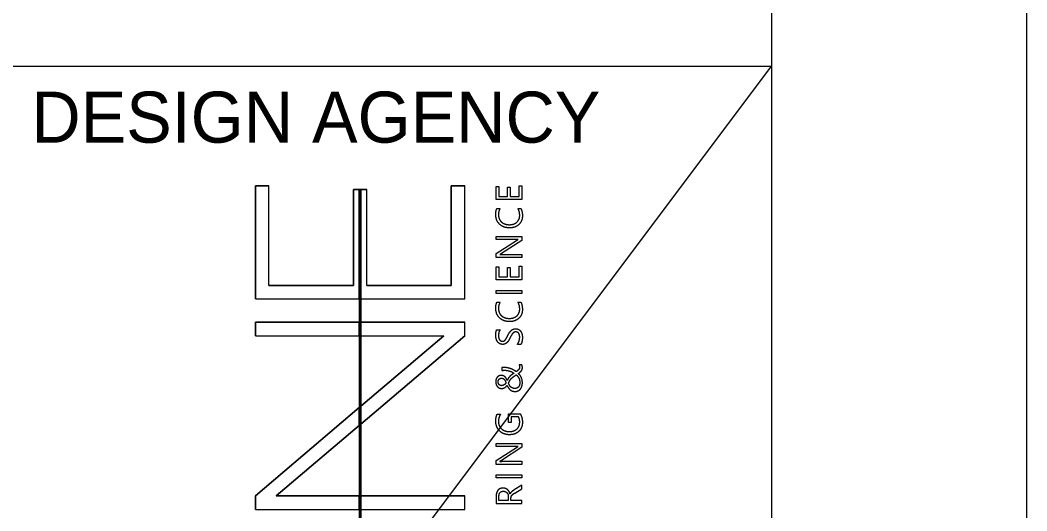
# Model space of a CAD drawing. Extents: x 0 to 34, y 0 to 30.9.
# Drawn here: x 32.028 to 34, y 4.129 to 5.09 of the extents above; entities that cross this region are included whole.
import ezdxf

# ---------------------------------------------------------------- set-up
doc = ezdxf.new("R2010")
doc.units = 0
for name, color, linetype in [('SC_Scratch1', 7, 'Continuous'), ('SH_Border', 7, 'Continuous'), ('SH_Cut_Line', 7, 'Continuous'), ('SH_Data', 7, 'Continuous')]:
    doc.layers.add(name, color=color, linetype=linetype)

msp = doc.modelspace()

# ---------------------------------------------------------------- linework, layer by layer
at = {"layer": 'SC_Scratch1'}
msp.add_line((32, 3), (33.5, 5), dxfattribs=at)
at = {"layer": 'SH_Border'}
msp.add_line((32, 5), (33.5, 5), dxfattribs=at)
msp.add_lwpolyline([(1.5, 21.5), (33.5, 21.5), (33.5, 0.5), (1.5, 0.5)], close=True, dxfattribs=at)
at = {"layer": 'SH_Cut_Line'}
msp.add_lwpolyline([(0, 0), (34, 0), (34, 22), (0, 22)], close=True, dxfattribs=at)
at = {"layer": 'SH_Data'}
for p, q in [((32.489, 4.7652), (32.5153, 4.7652)), ((32.489, 4.5439), (32.489, 4.7652)), ((32.5153, 4.5702), (32.5153, 4.7652)), ((32.6807, 4.5702), (32.6807, 4.7581)), ((32.6807, 4.7581), (32.6923, 4.7581)), ((32.6923, 4.7581), (32.6923, 3.9731)), ((32.6923, 4.7581), (32.6923, 4.5439)), ((32.6923, 4.7581), (32.6954, 4.7581)), ((32.6954, 4.7581), (32.6954, 3.9731)), ((32.6954, 4.7581), (32.6954, 4.5439)), ((32.6954, 4.7581), (32.707, 4.7581)), ((32.707, 4.5702), (32.707, 4.7581)), ((32.8724, 4.7652), (32.8988, 4.7652)), ((32.8724, 4.5702), (32.8724, 4.7652)), ((32.8988, 4.5439), (32.8988, 4.7652)), ((32.9617, 4.7208), (32.968, 4.7208)), ((33.0032, 4.7208), (33.0089, 4.7208)), ((33.0035, 4.6602), (33.0035, 4.6603)), ((32.9676, 4.631), (32.9676, 4.6308)), ((32.5153, 4.5702), (32.6807, 4.5702)), ((32.707, 4.5702), (32.8724, 4.5702)), ((32.489, 4.5439), (32.6923, 4.5439)), ((32.6954, 4.5439), (32.8988, 4.5439)), ((32.9617, 4.5373), (32.968, 4.5373)), ((33.0032, 4.5373), (33.0089, 4.5373)), ((32.489, 4.4717), (32.489, 4.4981)), ((32.489, 4.4981), (32.6923, 4.4981)), ((32.6923, 4.4981), (32.6923, 4.4717)), ((32.6954, 4.4981), (32.6954, 4.4717)), ((32.6954, 4.4981), (32.8988, 4.4981)), ((32.8988, 4.4717), (32.8988, 4.4981)), ((32.9615, 4.4834), (32.9681, 4.4834)), ((32.489, 4.4717), (32.6923, 4.4717)), ((32.6954, 4.3337), (32.8577, 4.4717)), ((32.8988, 4.4717), (32.6954, 4.2989)), ((32.6954, 4.4717), (32.8577, 4.4717)), ((33.009, 4.4549), (33.002, 4.4549)), ((32.9715, 4.4092), (32.9715, 4.4036)), ((33.0109, 4.4148), (33.0055, 4.4148)), ((33.0118, 4.4094), (33.0118, 4.4094)), ((32.9709, 4.3886), (32.9709, 4.3886)), ((33.0068, 4.3798), (33.0068, 4.3798)), ((32.489, 4.158), (32.6923, 4.331)), ((32.6923, 4.331), (32.6923, 4.2962)), ((32.6954, 4.3337), (32.6954, 4.2989)), ((32.9623, 4.318), (32.9689, 4.318)), ((32.6923, 4.2962), (32.5296, 4.158)), ((33.0035, 4.255), (33.0035, 4.2551)), ((32.9676, 4.2258), (32.9676, 4.2256)), ((32.9877, 4.1622), (32.9876, 4.1622)), ((32.489, 4.1316), (32.489, 4.158)), ((32.5296, 4.158), (32.6923, 4.158)), ((32.6923, 4.158), (32.6923, 4.1316)), ((32.6954, 4.158), (32.6954, 4.1316)), ((32.6954, 4.158), (32.8988, 4.158)), ((32.8988, 4.1316), (32.8988, 4.158)), ((32.489, 4.1316), (32.6923, 4.1316)), ((32.6954, 4.1316), (32.8988, 4.1316))]:
    msp.add_line(p, q, dxfattribs=at)
for points in [[(32.489, 4.7652), (32.489, 4.5439), (32.6923, 4.5439), (32.6923, 4.7581), (32.6807, 4.7581), (32.6807, 4.5702), (32.5153, 4.5702), (32.5153, 4.7652)], [(32.707, 4.5702), (32.707, 4.7581), (32.6954, 4.7581), (32.6954, 4.5439), (32.8988, 4.5439), (32.8988, 4.7652), (32.8724, 4.7652), (32.8724, 4.5702)], [(33.011, 4.7652), (33.011, 4.7384), (32.9605, 4.7384), (32.9605, 4.7641), (32.9659, 4.7641), (32.9659, 4.7443), (32.9827, 4.7443), (32.9827, 4.7626), (32.988, 4.7626), (32.988, 4.7443), (33.0057, 4.7443), (33.0057, 4.7652)], [(33.011, 4.6081), (33.011, 4.5813), (32.9605, 4.5813), (32.9605, 4.607), (32.9659, 4.607), (32.9659, 4.5873), (32.9827, 4.5873), (32.9827, 4.6055), (32.988, 4.6055), (32.988, 4.5873), (33.0057, 4.5873), (33.0057, 4.6081)], [(33.011, 4.5607), (33.011, 4.5548), (32.9605, 4.5548), (32.9605, 4.5607)], [(32.489, 4.4981), (32.489, 4.4717), (32.6923, 4.4717), (32.6923, 4.4981)], [(32.6954, 4.4981), (32.6954, 4.4717), (32.8577, 4.4717), (32.6954, 4.3337), (32.6954, 4.2989), (32.8988, 4.4717), (32.8988, 4.4981)], [(32.489, 4.158), (32.489, 4.1316), (32.6923, 4.1316), (32.6923, 4.158), (32.5296, 4.158), (32.6923, 4.2962), (32.6923, 4.331)], [(33.011, 4.1993), (33.011, 4.1934), (32.9605, 4.1934), (32.9605, 4.1993)], [(32.6954, 4.158), (32.6954, 4.1316), (32.8988, 4.1316), (32.8988, 4.158)]]:
    msp.add_lwpolyline(points, close=True, dxfattribs=at)
for points in [[(32.8317, 3.9686), (32.6986, 3.9356), (32.6986, 3.9731), (32.6954, 3.9731), (32.6954, 4.7581), (32.6923, 4.7581), (32.6923, 3.9731), (32.6891, 3.9731), (32.6891, 3.9333), (32.6149, 3.9149)], [(32.9961, 4.66), (32.9605, 4.66), (32.9605, 4.6659), (33.011, 4.6659), (33.011, 4.6586), (32.9708, 4.6326)], [(32.9745, 4.6311), (33.011, 4.6311), (33.011, 4.6252), (32.9605, 4.6252), (32.9605, 4.6328), (33.0001, 4.6581)], [(33.0042, 4.3131), (32.99, 4.3131), (32.99, 4.302), (32.9847, 4.302), (32.9847, 4.319), (33.0076, 4.319)], [(32.9961, 4.2547), (32.9605, 4.2547), (32.9605, 4.2607), (33.011, 4.2607), (33.011, 4.2534), (32.9708, 4.2274)], [(32.9745, 4.2258), (33.011, 4.2258), (33.011, 4.2199), (32.9605, 4.2199), (32.9605, 4.2276), (33.0001, 4.2529)], [(32.9969, 4.1637), (33.011, 4.1721), (33.011, 4.1792), (32.9958, 4.1697)], [(32.9605, 4.158), (32.9605, 4.1429), (33.011, 4.1429), (33.011, 4.1489), (32.9895, 4.1489), (32.9895, 4.1537)], [(32.9842, 4.1569), (32.9842, 4.1489), (32.9659, 4.1489), (32.9659, 4.157)]]:
    msp.add_lwpolyline(points, dxfattribs=at)
for points in [[(32.9597, 4.7089), (32.9597, 4.7161), (32.9617, 4.7208)], [(32.968, 4.7208), (32.965, 4.7154), (32.965, 4.7089)], [(33.0066, 4.7077), (33.0066, 4.7153), (33.0032, 4.7208)], [(33.0089, 4.7208), (33.0119, 4.7152), (33.0119, 4.7069)], [(32.9671, 4.6904), (32.9597, 4.6977), (32.9597, 4.7089)], [(32.965, 4.7089), (32.965, 4.7002), (32.9708, 4.6947)], [(32.9708, 4.6947), (32.9766, 4.6893), (32.9864, 4.6893)], [(32.9864, 4.6893), (32.9956, 4.6893), (33.0011, 4.6944)], [(33.0011, 4.6944), (33.0066, 4.6994), (33.0066, 4.7077)], [(33.0119, 4.7069), (33.0119, 4.6961), (33.0049, 4.6896)], [(32.9867, 4.6831), (32.9746, 4.6831), (32.9671, 4.6904)], [(33.0049, 4.6896), (32.998, 4.6831), (32.9867, 4.6831)], [(33.0035, 4.6603), (33.0013, 4.66), (32.9961, 4.66)], [(33.0001, 4.6581), (33.0026, 4.6597), (33.0035, 4.6602)], [(32.9708, 4.6326), (32.9692, 4.6316), (32.9676, 4.631)], [(32.9676, 4.6308), (32.9692, 4.6311), (32.9745, 4.6311)], [(32.9597, 4.5253), (32.9597, 4.5325), (32.9617, 4.5373)], [(32.968, 4.5373), (32.965, 4.5318), (32.965, 4.5253)], [(33.0066, 4.5241), (33.0066, 4.5317), (33.0032, 4.5373)], [(33.0089, 4.5373), (33.0119, 4.5316), (33.0119, 4.5233)], [(32.9671, 4.5068), (32.9597, 4.5141), (32.9597, 4.5253)], [(32.965, 4.5253), (32.965, 4.5166), (32.9708, 4.5112)], [(33.0011, 4.5108), (33.0066, 4.5159), (33.0066, 4.5241)], [(33.0119, 4.5233), (33.0119, 4.5125), (33.0049, 4.506)], [(32.9867, 4.4995), (32.9746, 4.4995), (32.9671, 4.5068)], [(32.9708, 4.5112), (32.9766, 4.5057), (32.9864, 4.5057)], [(32.9864, 4.5057), (32.9956, 4.5057), (33.0011, 4.5108)], [(33.0049, 4.506), (32.998, 4.4995), (32.9867, 4.4995)], [(32.9597, 4.4725), (32.9597, 4.4799), (32.9615, 4.4834)], [(32.9681, 4.4834), (32.965, 4.4789), (32.965, 4.4719)], [(32.9832, 4.4721), (32.9845, 4.4748), (32.986, 4.4772)], [(32.986, 4.4772), (32.9875, 4.4797), (32.9893, 4.4815)], [(32.9893, 4.4815), (32.9911, 4.4833), (32.9933, 4.4844)], [(32.9951, 4.4784), (32.9936, 4.4775), (32.9924, 4.4759)], [(32.9933, 4.4844), (32.9955, 4.4855), (32.9983, 4.4855)], [(32.9987, 4.4793), (32.9967, 4.4793), (32.9951, 4.4784)], [(32.9983, 4.4855), (33.002, 4.4855), (33.0046, 4.484)], [(33.0045, 4.4766), (33.0025, 4.4793), (32.9987, 4.4793)], [(33.0066, 4.4684), (33.0066, 4.4739), (33.0045, 4.4766)], [(33.0046, 4.484), (33.0072, 4.4826), (33.0088, 4.4801)], [(33.0088, 4.4801), (33.0104, 4.4776), (33.0112, 4.4743)], [(32.9605, 4.466), (32.9597, 4.4692), (32.9597, 4.4725)], [(32.9629, 4.4604), (32.9613, 4.4629), (32.9605, 4.466)], [(32.9671, 4.4564), (32.9646, 4.458), (32.9629, 4.4604)], [(32.965, 4.4719), (32.965, 4.4699), (32.9654, 4.468)], [(32.9654, 4.468), (32.9658, 4.4661), (32.9667, 4.4645)], [(32.9667, 4.4645), (32.9677, 4.463), (32.9691, 4.4621)], [(32.9691, 4.4621), (32.9705, 4.4611), (32.9726, 4.4611)], [(32.9726, 4.4611), (32.9746, 4.4611), (32.976, 4.4618)], [(32.976, 4.4618), (32.9774, 4.4626), (32.9785, 4.464)], [(32.9818, 4.4586), (32.9802, 4.4569), (32.9781, 4.4559)], [(32.9785, 4.464), (32.9797, 4.4654), (32.9808, 4.4674)], [(32.9808, 4.4674), (32.9819, 4.4694), (32.9832, 4.4721)], [(32.9849, 4.4625), (32.9835, 4.4602), (32.9818, 4.4586)], [(32.9876, 4.4675), (32.9862, 4.4648), (32.9849, 4.4625)], [(32.99, 4.4721), (32.9888, 4.47), (32.9876, 4.4675)], [(32.9924, 4.4759), (32.9911, 4.4743), (32.99, 4.4721)], [(33.002, 4.4549), (33.0031, 4.4561), (33.0039, 4.4577)], [(33.0039, 4.4577), (33.0048, 4.4594), (33.0053, 4.4612)], [(33.0053, 4.4612), (33.0059, 4.4631), (33.0062, 4.465)], [(33.0062, 4.465), (33.0066, 4.4668), (33.0066, 4.4684)], [(33.0102, 4.4575), (33.0097, 4.4558), (33.009, 4.4549)], [(33.0111, 4.461), (33.0108, 4.4591), (33.0102, 4.4575)], [(33.0117, 4.4645), (33.0115, 4.4628), (33.0111, 4.461)], [(33.0112, 4.4743), (33.0119, 4.4711), (33.0119, 4.4675)], [(33.0119, 4.4675), (33.0119, 4.4663), (33.0117, 4.4645)], [(32.9732, 4.4549), (32.9697, 4.4549), (32.9671, 4.4564)], [(32.9781, 4.4559), (32.976, 4.4549), (32.9732, 4.4549)], [(32.9737, 4.4095), (32.9727, 4.4095), (32.9715, 4.4092)], [(32.9715, 4.4036), (32.9727, 4.4039), (32.9739, 4.404)], [(32.9762, 4.4096), (32.9748, 4.4096), (32.9737, 4.4095)], [(32.9739, 4.404), (32.9751, 4.4042), (32.9764, 4.4042)], [(32.9827, 4.409), (32.9794, 4.4096), (32.9762, 4.4096)], [(32.9764, 4.4042), (32.9816, 4.4042), (32.9864, 4.4027)], [(32.989, 4.4072), (32.9859, 4.4083), (32.9827, 4.409)], [(32.9864, 4.4027), (32.9912, 4.4013), (32.9952, 4.3984)], [(32.9948, 4.4045), (32.992, 4.406), (32.989, 4.4072)], [(32.9952, 4.3984), (32.9931, 4.397), (32.9912, 4.3956)], [(32.9998, 4.4014), (32.9975, 4.403), (32.9948, 4.4045)], [(33.0027, 4.4036), (33.0015, 4.4026), (32.9998, 4.4014)], [(33.0048, 4.4057), (33.004, 4.4047), (33.0027, 4.4036)], [(33.004, 4.3979), (33.0059, 4.3993), (33.0073, 4.4005)], [(33.007, 4.3947), (33.0055, 4.3965), (33.004, 4.3979)], [(33.0061, 4.4079), (33.0057, 4.4067), (33.0048, 4.4057)], [(33.0055, 4.4148), (33.0059, 4.4136), (33.0062, 4.4125)], [(33.0065, 4.4104), (33.0065, 4.409), (33.0061, 4.4079)], [(33.0062, 4.4125), (33.0065, 4.4114), (33.0065, 4.4104)], [(33.0073, 4.4005), (33.0087, 4.4017), (33.0098, 4.403)], [(33.0098, 4.403), (33.0108, 4.4043), (33.0113, 4.4059)], [(33.0116, 4.4121), (33.0114, 4.4135), (33.0109, 4.4148)], [(33.0113, 4.4059), (33.0118, 4.4074), (33.0118, 4.4094)], [(33.0118, 4.4094), (33.0118, 4.4107), (33.0116, 4.4121)], [(32.9604, 4.3867), (32.9597, 4.3844), (32.9597, 4.3817)], [(32.9597, 4.3817), (32.9597, 4.3789), (32.9604, 4.3765)], [(32.9626, 4.3906), (32.9612, 4.389), (32.9604, 4.3867)], [(32.966, 4.3931), (32.964, 4.3922), (32.9626, 4.3906)], [(32.9643, 4.3817), (32.9643, 4.3829), (32.9646, 4.3841)], [(32.9661, 4.3761), (32.9643, 4.3782), (32.9643, 4.3817)], [(32.9646, 4.3841), (32.965, 4.3853), (32.9658, 4.3863)], [(32.9658, 4.3863), (32.9666, 4.3873), (32.9679, 4.388)], [(32.9704, 4.3941), (32.9679, 4.3941), (32.966, 4.3931)], [(32.9679, 4.388), (32.9691, 4.3886), (32.9709, 4.3886)], [(32.9774, 4.3916), (32.9746, 4.3941), (32.9704, 4.3941)], [(32.9709, 4.3886), (32.974, 4.3886), (32.9761, 4.3864)], [(32.9761, 4.3864), (32.9781, 4.3843), (32.9797, 4.3798)], [(32.9822, 4.3844), (32.9802, 4.3892), (32.9774, 4.3916)], [(32.9797, 4.3798), (32.9791, 4.3786), (32.9782, 4.3776)], [(32.9845, 4.3888), (32.9831, 4.3868), (32.9822, 4.3844)], [(32.9876, 4.3925), (32.9859, 4.3908), (32.9845, 4.3888)], [(32.9847, 4.3788), (32.9857, 4.3815), (32.987, 4.3836)], [(32.9866, 4.3747), (32.9856, 4.3765), (32.9847, 4.3788)], [(32.987, 4.3836), (32.9882, 4.3857), (32.9899, 4.3876)], [(32.9912, 4.3956), (32.9893, 4.3941), (32.9876, 4.3925)], [(32.9899, 4.3876), (32.9917, 4.3894), (32.994, 4.3912)], [(32.994, 4.3912), (32.9964, 4.393), (32.9998, 4.3952)], [(32.9998, 4.3952), (33.0012, 4.3939), (33.0025, 4.3924)], [(33.0025, 4.3924), (33.0037, 4.3908), (33.0047, 4.3889)], [(33.0047, 4.3889), (33.0057, 4.387), (33.0063, 4.3848)], [(33.0068, 4.3798), (33.0068, 4.3775), (33.0062, 4.3754)], [(33.0063, 4.3848), (33.0068, 4.3825), (33.0068, 4.3798)], [(33.0095, 4.3906), (33.0084, 4.3928), (33.007, 4.3947)], [(33.0112, 4.3856), (33.0105, 4.3883), (33.0095, 4.3906)], [(33.0109, 4.3728), (33.0118, 4.376), (33.0118, 4.3798)], [(33.0118, 4.3798), (33.0118, 4.383), (33.0112, 4.3856)], [(32.9604, 4.3765), (32.9612, 4.3741), (32.9627, 4.3723)], [(32.9627, 4.3723), (32.9641, 4.3706), (32.9663, 4.3696)], [(32.9712, 4.374), (32.968, 4.3741), (32.9661, 4.3761)], [(32.9663, 4.3696), (32.9684, 4.3685), (32.9712, 4.3685)], [(32.9739, 4.3745), (32.9727, 4.374), (32.9712, 4.374)], [(32.9712, 4.3685), (32.9731, 4.3685), (32.9747, 4.3691)], [(32.9763, 4.3757), (32.9752, 4.3749), (32.9739, 4.3745)], [(32.9747, 4.3691), (32.9763, 4.3696), (32.9776, 4.3704)], [(32.9782, 4.3776), (32.9774, 4.3765), (32.9763, 4.3757)], [(32.9776, 4.3704), (32.979, 4.3712), (32.98, 4.3723)], [(32.98, 4.3723), (32.981, 4.3733), (32.9818, 4.3744)], [(32.9818, 4.3744), (32.9843, 4.3688), (32.9881, 4.3657)], [(32.9892, 4.3715), (32.9877, 4.3728), (32.9866, 4.3747)], [(32.9881, 4.3657), (32.9919, 4.3627), (32.9973, 4.3627)], [(32.9926, 4.3693), (32.9906, 4.3701), (32.9892, 4.3715)], [(32.9971, 4.3685), (32.9945, 4.3685), (32.9926, 4.3693)], [(33.0013, 4.3694), (32.9995, 4.3685), (32.9971, 4.3685)], [(32.9973, 4.3627), (33.0008, 4.3627), (33.0035, 4.3639)], [(33.0044, 4.3718), (33.0032, 4.3703), (33.0013, 4.3694)], [(33.0035, 4.3639), (33.0062, 4.3652), (33.0081, 4.3674)], [(33.0062, 4.3754), (33.0056, 4.3734), (33.0044, 4.3718)], [(33.0081, 4.3674), (33.0099, 4.3697), (33.0109, 4.3728)], [(33.0076, 4.319), (33.0119, 4.3114), (33.0119, 4.3021)], [(32.9597, 4.3041), (32.9597, 4.3124), (32.9623, 4.318)], [(32.9672, 4.2853), (32.9597, 4.2927), (32.9597, 4.3041)], [(32.9689, 4.318), (32.965, 4.3118), (32.965, 4.3035)], [(32.965, 4.3035), (32.965, 4.295), (32.9709, 4.2895)], [(33.0011, 4.2891), (33.0066, 4.2942), (33.0066, 4.3028)], [(33.0066, 4.3028), (33.0066, 4.3087), (33.0042, 4.3131)], [(33.0119, 4.3021), (33.0119, 4.2913), (33.0049, 4.2846)], [(32.9864, 4.2779), (32.9747, 4.2779), (32.9672, 4.2853)], [(32.9709, 4.2895), (32.9767, 4.2841), (32.986, 4.2841)], [(32.986, 4.2841), (32.9956, 4.2841), (33.0011, 4.2891)], [(33.0049, 4.2846), (32.9979, 4.2779), (32.9864, 4.2779)], [(33.0035, 4.2551), (33.0013, 4.2547), (32.9961, 4.2547)], [(33.0001, 4.2529), (33.0026, 4.2545), (33.0035, 4.255)], [(32.9708, 4.2274), (32.9692, 4.2264), (32.9676, 4.2258)], [(32.9676, 4.2256), (32.9692, 4.2258), (32.9745, 4.2258)], [(32.9613, 4.1641), (32.9605, 4.1613), (32.9605, 4.158)], [(32.9638, 4.169), (32.9622, 4.1669), (32.9613, 4.1641)], [(32.9681, 4.1722), (32.9655, 4.1711), (32.9638, 4.169)], [(32.9659, 4.157), (32.9659, 4.1619), (32.9681, 4.1646)], [(32.974, 4.1734), (32.9706, 4.1734), (32.9681, 4.1722)], [(32.9681, 4.1646), (32.9704, 4.1672), (32.9745, 4.1672)], [(32.9788, 4.1726), (32.9766, 4.1734), (32.974, 4.1734)], [(32.9745, 4.1672), (32.9767, 4.1672), (32.9785, 4.1664)], [(32.9785, 4.1664), (32.9803, 4.1656), (32.9816, 4.1643)], [(32.9827, 4.1703), (32.981, 4.1718), (32.9788, 4.1726)], [(32.9816, 4.1643), (32.9828, 4.1629), (32.9835, 4.161)], [(32.9857, 4.1668), (32.9845, 4.1689), (32.9827, 4.1703)], [(32.9835, 4.161), (32.9842, 4.1591), (32.9842, 4.1569)], [(32.9876, 4.1622), (32.9869, 4.1648), (32.9857, 4.1668)], [(32.989, 4.1644), (32.9883, 4.1635), (32.9877, 4.1622)], [(32.9907, 4.1662), (32.9897, 4.1653), (32.989, 4.1644)], [(32.9929, 4.1678), (32.9917, 4.167), (32.9907, 4.1662)], [(32.9912, 4.1592), (32.9921, 4.1603), (32.9935, 4.1614)], [(32.9958, 4.1697), (32.9942, 4.1687), (32.9929, 4.1678)], [(32.9935, 4.1614), (32.9949, 4.1625), (32.9969, 4.1637)], [(32.9895, 4.1537), (32.9895, 4.1554), (32.9899, 4.1567)], [(32.9899, 4.1567), (32.9904, 4.158), (32.9912, 4.1592)]]:
    msp.add_open_spline(points, degree=2, dxfattribs=at)

# ---------------------------------------------------------------- texts
msp.add_text('DESIGN AGENCY', height=0.1, dxfattribs=at).set_placement((32.05, 4.85))

doc.saveas('drawing.dxf')
